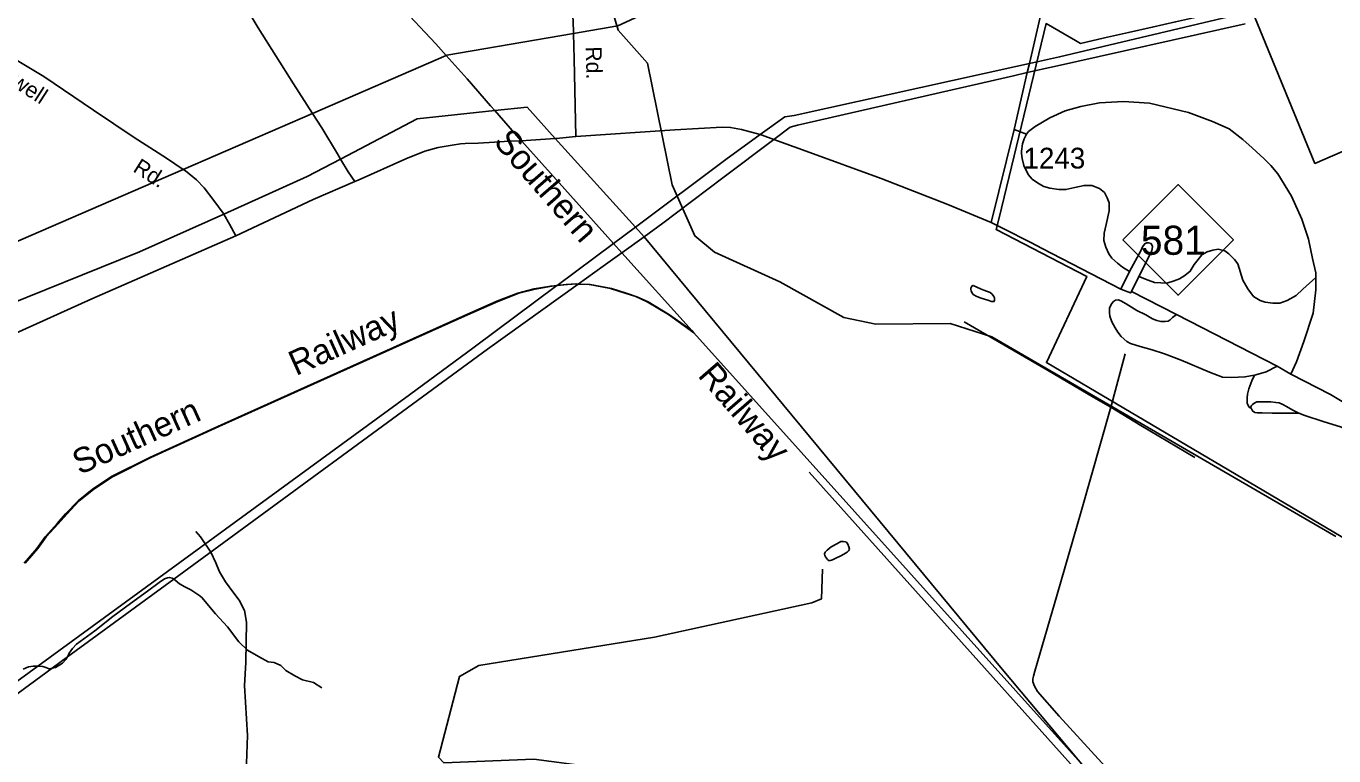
# Model space of a CAD drawing. Extents: x 2260773 to 2342389, y 552869 to 618546.
# Drawn here: x 2280360 to 2288230, y 598847 to 603238 of the extents above; entities that cross this region are included whole.
import ezdxf

# ---------------------------------------------------------------- set-up
doc = ezdxf.new("R2010")
doc.units = 0
for name, color, linetype in [('Exist Boundary Political City Limit New', 7, 'Continuous'), ('Exist Boundary Political Urban Extension UEB', 7, 'Continuous'), ('Exist Hydrographic Creek Single Shore', 7, 'Continuous'), ('Exist Hydrographic Misc Water Feature', 7, 'Continuous'), ('Exist Railroad Mainline', 7, 'Continuous'), ('Exist Railroad Mainline Label', 7, 'Continuous'), ('Exist Railroad Siding', 7, 'Continuous'), ('Exist Road Non-System Type 51', 7, 'Continuous'), ('Exist Road Primary NC Attributed', 7, 'Continuous'), ('Exist Road Primary NC Shield CELL', 7, 'Continuous'), ('Exist Road Primary NC Shield Number Label', 7, 'Continuous'), ('Exist Road Secondary Type 51 Attributed', 7, 'Continuous'), ('Exist Road Secondary Type 51 Label', 7, 'Continuous'), ('Exist Road Secondary Type 51 Number Label', 7, 'Continuous'), ('Exist Utilities Electrical Transmission Line', 7, 'Continuous'), ('Map Preparation Boundary City Limit Buffer Line', 7, 'Continuous')]:
    doc.layers.add(name, color=color, linetype=linetype)

msp = doc.modelspace()

# ---------------------------------------------------------------- linework, layer by layer
at = {"layer": 'Exist Boundary Political City Limit New'}
msp.add_lwpolyline([(2288484.5, 600042.1), (2286500, 601213.4), (2286743.2, 601732.2), (2286198.5, 602014.4), (2286215.2, 602083.9), (2286498, 603253.8), (2286675.8, 603151.9), (2286705.2, 603134.9), (2286849.8, 603167.4), (2286994.2, 603200), (2287137, 603232.2), (2287277.5, 603263.9), (2287421.5, 603296.4), (2287566, 603329), (2287724.2, 603364.7), (2288116, 602412), (2288435.5, 602550.4)], dxfattribs=at)
at = {"layer": 'Exist Boundary Political Urban Extension UEB'}
for p, q in [((2283544.6, 602562.6), (2284026.3, 602029)), ((2284026.3, 602029), (2284079.1, 601970.5))]:
    msp.add_line(p, q, dxfattribs=at)
for points in [[(2283180.3, 602730.4), (2283374.6, 602750.9), (2283544.6, 602562.6)], [(2282251.6, 602438.5), (2282713, 602681.3), (2283180.3, 602730.4)], [(2281548.7, 602107.8), (2282051.3, 602333.1), (2282251.6, 602438.5)], [(2279105.8, 601336.1), (2279230.5, 601149.2), (2281041.4, 601880.4), (2281548.7, 602107.8)], [(2284079.1, 601970.5), (2286234.2, 599368.4), (2286857.2, 598623.6)]]:
    msp.add_lwpolyline(points, dxfattribs=at)
at = {"layer": 'Exist Hydrographic Creek Single Shore'}
for points in [[(2288241.8, 600166.2), (2286172.8, 601369.1), (2285921.9, 601449.6), (2285472.8, 601445.6), (2285280.7, 601485.5), (2284895.8, 601700), (2284502.7, 601878.5), (2284384.8, 601976), (2284248.6, 602283.7), (2284099.8, 603014.8), (2283923.6, 603215.1), (2283845.7, 603472.5), (2284045.6, 604380.1), (2283991.7, 604787.9), (2283797.7, 605087.1), (2283384.7, 605633.3), (2283178.7, 606204.8), (2283010.7, 606362.3), (2282767.7, 606508.3)], [(2286243.8, 593850.9), (2286225.7, 594008.7), (2285935.8, 594772.2), (2285951.8, 595654), (2285602.8, 596490.8), (2285254.8, 597153.8), (2284792.8, 597576.4), (2284607.7, 597790), (2284099.8, 598594), (2283982.7, 598724.2), (2283764.7, 598781.1), (2283414.7, 598827.5), (2282873.8, 598805.7), (2282840.7, 598839.2), (2282968.7, 599325.2), (2283084.8, 599391.8), (2284140.8, 599560.6), (2285088.7, 599767.7), (2285146.8, 599792.7), (2285153.7, 599969.7)]]:
    msp.add_lwpolyline(points, dxfattribs=at)
at = {"layer": 'Exist Hydrographic Misc Water Feature'}
for points in [[(2286103.5, 601656.7), (2286081.2, 601668.2), (2286059, 601678.1), (2286051, 601674), (2286049.6, 601670.1), (2286045.3, 601662.3), (2286045.7, 601654.1), (2286047.8, 601646.1), (2286052.1, 601636.1), (2286059.9, 601624), (2286082.2, 601610.5), (2286108.2, 601600.5), (2286148, 601589.2), (2286170, 601581.4), (2286176.3, 601581.3), (2286184.5, 601581.3), (2286188, 601587.2), (2286188, 601595.3), (2286188.2, 601603.4), (2286183.5, 601611.4), (2286173.5, 601625.1), (2286162, 601635), (2286123.4, 601648.9), (2286103.5, 601656.7)], [(2281382, 600196.8), (2281409.9, 600165), (2281471, 600071.9), (2281501.5, 600008.1), (2281524.1, 599954.4), (2281560.4, 599894.6), (2281603.3, 599835), (2281641.4, 599783.4), (2281674, 599721.8), (2281685.1, 599652), (2281681.4, 599408), (2281674.6, 599270.3), (2281691, 598968.6), (2281683.6, 598744.6), (2281676.3, 598450.5), (2281681.2, 598304.6), (2281672.2, 598198.9), (2281669.9, 598082.8), (2281672.2, 598012.7), (2281682.6, 597962.9), (2281707, 597905.3)], [(2285193.7, 600020.8), (2285213, 600027.3), (2285233.3, 600037.1), (2285263, 600051.8), (2285281.3, 600061.5), (2285300.8, 600072), (2285309, 600080.1), (2285312.9, 600086), (2285314.9, 600090.2), (2285310.6, 600105.8), (2285304.6, 600120.1), (2285296.2, 600133.9), (2285290.1, 600135.7), (2285276.6, 600137.7), (2285264, 600137.6), (2285238.4, 600123.2), (2285204.8, 600105.1), (2285181, 600084.8), (2285168.7, 600072.8), (2285165, 600062.5), (2285167.1, 600052.8), (2285171.4, 600044.5), (2285183.1, 600028.9), (2285193.7, 600020.8)]]:
    msp.add_lwpolyline(points, dxfattribs=at)
at = {"layer": 'Exist Railroad Mainline'}
msp.add_line((2284378.9, 601393.8), (2284368.5, 601405.4), dxfattribs=at)
for points in [[(2283339.6, 602549.2), (2283180.3, 602730.4), (2283154.7, 602759.6), (2283013.2, 602922.3), (2282888.6, 603061.7), (2282825.4, 603132.4), (2282603.2, 603368.2), (2282433.6, 603560.6), (2282271.8, 603747), (2282045.7, 603992.7), (2281744.6, 604327.7), (2281506.4, 604579.3), (2281381.3, 604706), (2281286.5, 604793.1), (2281212.1, 604860.4), (2281147.6, 604913.8), (2281105.1, 604951.3), (2281042.9, 604994.7), (2280956.2, 605051.9), (2280885.9, 605103.3), (2279466.6, 606053.8)], [(2284368.5, 601405.4), (2283945.9, 601875.1), (2283895.4, 601931.3), (2283342.6, 602545.7), (2283339.6, 602549.2)], [(2287893.8, 597482.5), (2286781.2, 598720.6), (2286638.8, 598879), (2284378.9, 601393.8)]]:
    msp.add_lwpolyline(points, dxfattribs=at)
at = {"layer": 'Exist Railroad Siding'}
for points in [[(2283750, 601683.7), (2283748.4, 601684), (2283683, 601686.6), (2283668.5, 601687.2), (2283610.5, 601684.6), (2283556.1, 601678.3), (2283516.7, 601673.7), (2283417, 601656.7), (2283319.3, 601631.9), (2283191.7, 601582.7), (2282990.6, 601492.8), (2281513.7, 600829.3), (2281103.7, 600643.5), (2280873, 600527.4), (2280757.7, 600450.4), (2280672.3, 600381.7), (2280597.1, 600302.9), (2280545.8, 600244.5), (2280474.6, 600165.8), (2280423.2, 600095.5), (2280348, 600006.8)], [(2283750, 601683.7), (2283682.7, 601686.4), (2283675.1, 601686.7), (2283617.1, 601684.1), (2283554.1, 601676.8), (2283523.3, 601673.2), (2283423.6, 601656.2), (2283325.9, 601631.4), (2283198.3, 601582.2), (2282997.2, 601492.3), (2281520.3, 600828.8), (2281110.3, 600643), (2280879.6, 600526.9), (2280764.3, 600449.9), (2280678.9, 600381.2), (2280603.7, 600302.4), (2280552.4, 600244), (2280481.2, 600165.3), (2280429.8, 600095), (2280354.6, 600006.3)], [(2284368.5, 601405.4), (2284232.5, 601502), (2284103.9, 601578.6), (2284035.6, 601610), (2283971.5, 601631.5), (2283883.2, 601658.7), (2283755, 601683.5), (2283750, 601683.7)], [(2284378.9, 601393.8), (2284225.9, 601502.5), (2284097.3, 601579.1), (2284029, 601610.5), (2283964.9, 601632), (2283876.6, 601659.2), (2283750, 601683.7)]]:
    msp.add_lwpolyline(points, dxfattribs=at)
at = {"layer": 'Exist Road Non-System Type 51'}
for p, q in [((2286306.3, 602615.5), (2286379.7, 602588.5)), ((2286378.7, 602584.3), (2286380.6, 602588.2)), ((2286379.7, 602588.5), (2286380.6, 602588.2)), ((2286949, 601655.9), (2286999.9, 601762.5)), ((2287011.9, 601642.1), (2287056.3, 601730.9)), ((2286900.4, 600990.6), (2286975, 601267.1)), ((2286888, 600944.7), (2286899.6, 600987.7)), ((2286899.6, 600987.7), (2286900.4, 600990.6)), ((2285072.4, 600554.9), (2286594.7, 598855.2)), ((2286594.7, 598855.2), (2286696, 598742.1))]:
    msp.add_line(p, q, dxfattribs=at)
for points in [[(2281036.8, 603990.4), (2281121.5, 604000.1), (2281177.2, 604007.4), (2281211.1, 604009.8), (2281230.5, 604007.4), (2281252.3, 604002.6), (2281271.6, 603992.9), (2281293.4, 603961.4), (2281361.2, 603852.4), (2281433.9, 603762.7), (2281472.6, 603702.2), (2281542.8, 603585.9), (2281755.9, 603227.4), (2281968.9, 602890.7), (2282083, 602712.9)], [(2286380.6, 602588.2), (2286392.5, 602604.3), (2286432.1, 602634.7), (2286521.5, 602687.5), (2286613.1, 602728.2), (2286706.8, 602755.1), (2286820.6, 602776.1), (2286964.3, 602785.4), (2287120.5, 602775.1), (2287354.8, 602719.3), (2287499.3, 602664.6), (2287599.5, 602619.6), (2287682.2, 602556.3), (2287738.6, 602507), (2287811.2, 602439.7), (2287851.6, 602400.1), (2287894, 602350.5), (2287975.2, 602215.3), (2288038.5, 602076), (2288077.5, 601956.5), (2288102.7, 601840.6), (2288121.5, 601752.9), (2288121.8, 601724.9)], [(2282083, 602712.9), (2282138.4, 602626.6), (2282232.8, 602469.2), (2282251.6, 602438.5)], [(2286351, 602471.4), (2286349.5, 602485.8), (2286357.2, 602529.8), (2286366.8, 602560), (2286378.7, 602584.3)], [(2282251.6, 602438.5), (2282298.2, 602362.6), (2282337.8, 602303)], [(2286999.9, 601762.5), (2286957.7, 601787.9), (2286927.6, 601811.7), (2286893.4, 601841.4), (2286877, 601869.1), (2286858.8, 601908.9), (2286846.4, 601948.9), (2286847.9, 601992.9), (2286859.3, 602044.8), (2286878.6, 602127), (2286878.2, 602175), (2286866, 602204.8), (2286849.6, 602236.7), (2286819.4, 602262.4), (2286773.1, 602279.9), (2286727.4, 602279.6), (2286671.3, 602267), (2286617.5, 602254.5), (2286575.5, 602256.1), (2286521.5, 602263.6), (2286485.5, 602273.3), (2286453.3, 602291), (2286415.1, 602318.5), (2286390.8, 602346.4), (2286364.3, 602400.1), (2286354, 602441.9), (2286351, 602471.4)], [(2286999.9, 601762.5), (2287070.7, 601891), (2287078.5, 601911), (2287092.3, 601929.1), (2287104.2, 601935.3), (2287114.2, 601935.3), (2287130.3, 601929.6), (2287138.5, 601911.6), (2287134.8, 601885.7), (2287056.3, 601730.9)], [(2287056.3, 601730.9), (2287112.4, 601709.4), (2287150.5, 601695.8), (2287188.5, 601694.3), (2287224.4, 601692.5), (2287268.3, 601704.8), (2287302.3, 601717.3), (2287334.1, 601737.5), (2287365.8, 601763.8), (2287389.4, 601803.9), (2287413, 601834.2), (2287436.8, 601862.4), (2287468.6, 601880.7), (2287502.6, 601891), (2287534.4, 601895.4), (2287574.4, 601885.7), (2287598.7, 601867.9), (2287633, 601834.4), (2287653.2, 601808.6), (2287682.2, 601708.8), (2287712.5, 601657.2), (2287747, 601611.5), (2287787.1, 601587.9), (2287817.3, 601578.1), (2287863.3, 601570.6), (2287905.3, 601570.9), (2287949, 601587.4), (2288002.8, 601617.9), (2288044.4, 601656.3), (2288121.8, 601724.9)], [(2288121.8, 601724.9), (2288122.5, 601650.9), (2288105.8, 601510.9), (2288050.5, 601341.1), (2288005.5, 601219.1), (2287972.1, 601143.6)], [(2287284.2, 601503.8), (2287259.5, 601484.9), (2287245, 601471.8), (2287233.4, 601463.1), (2287214.5, 601460.2), (2287189.8, 601461.7), (2287165.2, 601467.5), (2287139, 601477.6), (2287098.4, 601500.9), (2287044.7, 601527), (2286979.4, 601567.7), (2286947.5, 601585.1), (2286931.5, 601590.9), (2286917, 601589.4), (2286903.9, 601582.2), (2286892.3, 601567.7), (2286880.7, 601541.5), (2286879.3, 601513.9), (2286882.2, 601493.6), (2286894.8, 601459.5), (2286913.3, 601423.7), (2286929.4, 601397.8), (2286950.4, 601371.6), (2286985.2, 601339.7), (2287007, 601328.1), (2287065, 601310.6), (2287136.1, 601290.3), (2287210.2, 601267.1), (2287311.7, 601229.3), (2287481.5, 601155.3), (2287559.9, 601126.2), (2287613.6, 601124.8), (2287694.9, 601127.7), (2287753.7, 601137.9)], [(2286888, 600944.7), (2286786.4, 601002.8), (2286506.3, 601168.3), (2286005.6, 601458.7)], [(2287753.7, 601137.9), (2287761.6, 601139.3), (2287822.6, 601158.2), (2287889.4, 601191.6)], [(2287753.7, 601137.9), (2287737, 601104.4), (2287719.6, 601056.5), (2287710.9, 601024.6), (2287709.4, 601001.3), (2287708, 600985.4), (2287709.4, 600969.4), (2287716.7, 600952), (2287722.5, 600943.2), (2287732.6, 600938.9)], [(2286888, 600944.7), (2286709.5, 600317.4), (2286564.3, 599817.9), (2286445.3, 599405.5), (2286431, 599357.1)], [(2286888, 600944.7), (2287069.4, 600834.3), (2287393, 600642.7)], [(2288020, 600908.4), (2287983.7, 600927.3), (2287944.5, 600949.1), (2287924.2, 600960.7), (2287901, 600970.8), (2287880.7, 600973.7), (2287851.6, 600976.6), (2287822.6, 600978.1), (2287792.1, 600976.6), (2287767.5, 600976.6), (2287754.4, 600970.8), (2287741.3, 600962.1), (2287734.1, 600954.9), (2287731.2, 600947.6), (2287732.6, 600938.9)], [(2287732.6, 600938.9), (2287741.3, 600922.9), (2287754.4, 600914.2), (2287770.4, 600911.3), (2287799.4, 600911.3), (2287858.9, 600909.8), (2287943.1, 600908.4), (2288020, 600908.4)], [(2288020, 600908.4), (2288054.8, 600895.3), (2288165.1, 600859), (2288276.9, 600825.6), (2288308.8, 600811.1), (2288332, 600802.4), (2288348, 600795.1), (2288366.8, 600793.7), (2288387.2, 600793.7), (2288414.7, 600795.1), (2288435.1, 600799.5), (2288455.4, 600811.1), (2288478.6, 600822.7), (2288498.9, 600834.3)], [(2280609.5, 599442.4), (2280610.8, 599444.5), (2280619, 599466), (2280638.9, 599492.5), (2280663.7, 599519), (2280772.9, 599598.5), (2280882.1, 599686.2), (2280988, 599764), (2281090.6, 599838.5), (2281160.1, 599889.9), (2281193.2, 599913), (2281209.8, 599918), (2281223, 599921.3), (2281237.9, 599916.4), (2281247.7, 599910.1)], [(2281247.7, 599910.1), (2281256.1, 599904.8), (2281282.6, 599883.2), (2281314, 599865), (2281350.4, 599845.2), (2281405, 599810.4), (2281419.9, 599798.8), (2281446.4, 599764), (2281499.3, 599701.1), (2281572.1, 599623.3), (2281640, 599532.3), (2281691.3, 599482.6), (2281759.1, 599444.5), (2281815.4, 599413.1), (2281853.4, 599408.1), (2281893.1, 599389.9), (2281922.9, 599361.7), (2281975.9, 599328.6), (2282022.2, 599303.8), (2282090, 599288.9), (2282139.7, 599257.4)], [(2280516.9, 599374.7), (2280536.3, 599378.3), (2280552.9, 599388.2), (2280572.7, 599401.5), (2280579.3, 599404.8), (2280599.2, 599426.3), (2280609.5, 599442.4)], [(2280342.7, 599368.4), (2280374.1, 599383.3), (2280402.3, 599386.6), (2280428.8, 599386.6), (2280429.1, 599386.5)], [(2280429.1, 599386.5), (2280460.2, 599384.9), (2280478.4, 599378.3), (2280498.2, 599371.7), (2280509.8, 599373.3), (2280516.9, 599374.7)], [(2286431, 599357.1), (2286422.1, 599327), (2286417.7, 599309.6), (2286419.2, 599292.2), (2286427.9, 599266.1), (2286446, 599234.4), (2286577.4, 599085.8), (2287112.7, 598501.1), (2287480.9, 598094.7)]]:
    msp.add_lwpolyline(points, dxfattribs=at)
at = {"layer": 'Exist Road Primary NC Attributed'}
for points in [[(2283668.5, 602574.1), (2283570, 602564.4), (2283544.6, 602562.6), (2283397.2, 602552.1), (2283339.6, 602549.2)], [(2286167.6, 602056.5), (2285907.2, 602165.6), (2285505.3, 602322.2), (2285054.9, 602485.3), (2284860.3, 602556.6), (2284790.2, 602582.2), (2284778.5, 602585.4), (2284666, 602616.1), (2284599.8, 602629), (2284548.1, 602630.7), (2284264.1, 602614.5), (2283668.5, 602574.1)], [(2283339.6, 602549.2), (2283266.5, 602545.5), (2283179.4, 602539.4), (2283080.2, 602534.6), (2283002.7, 602532.1), (2282973.6, 602529.7), (2282924.1, 602522.9), (2282839.6, 602509), (2282758.5, 602485.9), (2282644.4, 602439.5), (2282357.3, 602312.4), (2282337.8, 602303), (2282086.7, 602194.5), (2281621.8, 601975.9)], [(2289571.4, 598974.2), (2289374.1, 599312.5), (2289105.2, 599815.2), (2288844.6, 600320.5), (2288699.2, 600577.3), (2288644, 600671.7), (2288578.5, 600755.7), (2288535.2, 600803.8), (2288498.9, 600834.3), (2288455.4, 600870.6), (2288365.4, 600928.7), (2288210.1, 601021.7), (2287972.1, 601143.6), (2287889.4, 601191.6), (2287284.2, 601503.8), (2287011.9, 601642.1), (2287007.1, 601632.6), (2286949, 601655.9), (2286475.6, 601901), (2286406.7, 601936.7), (2286240.2, 602020.1), (2286239.7, 602020.4), (2286167.6, 602056.5)], [(2281621.8, 601975.9), (2280754.7, 601596.8), (2280274.9, 601381.6), (2279715.8, 601136.3), (2279285.4, 600941.2), (2279144.7, 600873.3)]]:
    msp.add_lwpolyline(points, dxfattribs=at)
at = {"layer": 'Exist Road Primary NC Shield CELL'}
msp.add_lwpolyline([(2286959.9, 601952.1), (2287292.9, 602285.1), (2287625.9, 601952.1), (2287292.9, 601619.1)], close=True, dxfattribs=at)
at = {"layer": 'Exist Road Secondary Type 51 Attributed'}
for points in [[(2283033.1, 604532.5), (2283142.8, 604360.3), (2283239.2, 604205.2), (2283376.3, 603987.2), (2283495.8, 603790.2), (2283562, 603649.7), (2283594.2, 603564.1), (2283623.3, 603483.3), (2283637.8, 603399.4), (2283652.3, 603271.8), (2283654.5, 603194.6), (2283658.8, 603040.9), (2283668.5, 602574.1)], [(2286485.2, 603390.4), (2286468.6, 603318.6), (2286398.2, 603013.5), (2286385.5, 602958.7), (2286306.3, 602615.5), (2286167.6, 602056.5)], [(2281621.8, 601975.9), (2281584.3, 602045.8), (2281548.7, 602107.8), (2281546.2, 602112.1), (2281489.9, 602189.9), (2281432, 602266), (2281385.7, 602314.1), (2281319.5, 602367), (2281305.7, 602376.5), (2281205.3, 602444.8), (2281010.1, 602569), (2280765.2, 602732.9), (2280465.7, 602934.9), (2280215.8, 603085.6), (2280032.2, 603184.9), (2279931.9, 603235.1)]]:
    msp.add_lwpolyline(points, dxfattribs=at)
at = {"layer": 'Exist Utilities Electrical Transmission Line'}
for p, q in [((2282888.6, 603061.7), (2282083, 602712.9)), ((2286398.2, 603013.5), (2286315.6, 602995.3)), ((2286385.5, 602958.7), (2286475.7, 602979.2)), ((2286489, 603033.6), (2286398.2, 603013.5)), ((2286302.2, 602939.6), (2286385.5, 602958.7)), ((2282083, 602712.9), (2281305.7, 602376.5)), ((2283895.4, 601931.3), (2284026.3, 602029)), ((2284079.1, 601970.5), (2283945.9, 601875.1)), ((2283556.1, 601678.3), (2283895.4, 601931.3)), ((2283554.1, 601676.8), (2283556.1, 601678.3)), ((2283683, 601686.6), (2283682.7, 601686.4)), ((2280609.5, 599442.4), (2281247.7, 599910.1)), ((2280516.9, 599374.7), (2280609.5, 599442.4))]:
    msp.add_line(p, q, dxfattribs=at)
for points in [[(2285134.4, 603802.1), (2283921.7, 603240.7), (2283654.5, 603194.6)], [(2287673.1, 603313), (2286580.1, 603053.7), (2286489, 603033.6)], [(2286475.7, 602979.2), (2286482.9, 602980.9), (2286530.7, 602991.4), (2287696.4, 603252.2)], [(2283654.5, 603194.6), (2282891.9, 603063.1), (2282888.6, 603061.7)], [(2286315.6, 602995.3), (2284982.2, 602700.9), (2284926.4, 602692.5), (2284778.5, 602585.4)], [(2286302.2, 602939.6), (2285002.8, 602643.1), (2284959, 602630.8), (2284860.3, 602556.6)], [(2284026.3, 602029), (2284570.9, 602435.2), (2284778.5, 602585.4)], [(2284860.3, 602556.6), (2284552.1, 602325), (2284192.7, 602051.8), (2284079.1, 601970.5)], [(2281305.7, 602376.5), (2279648.8, 601659.3), (2279613.1, 601641), (2279579.3, 601622.7), (2279523.7, 601582.2), (2279105.8, 601336.1)], [(2283945.9, 601875.1), (2283833.4, 601794.6), (2283683, 601686.6)], [(2280429.1, 599386.5), (2282667.3, 601020), (2283056.4, 601305.6), (2283554.1, 601676.8)], [(2283682.7, 601686.4), (2283136.5, 601294.3), (2281247.7, 599910.1)], [(2280429.1, 599386.5), (2279945.4, 599033.6), (2279554.2, 598762), (2276202.5, 597215.3), (2273346.6, 595901.2), (2272928.5, 595719.3), (2272512.5, 595535.4), (2272145.9, 595392.1), (2272049.1, 595358.1)], [(2272051.3, 595276.1), (2272178.6, 595328.5), (2272535, 595473.8), (2272963.1, 595651.7), (2273381.1, 595845.5), (2276661.1, 597333.5), (2279596.8, 598700.4), (2280516.9, 599374.7)]]:
    msp.add_lwpolyline(points, dxfattribs=at)
at = {"layer": 'Map Preparation Boundary City Limit Buffer Line'}
msp.add_lwpolyline([(2288484.5, 600042.1), (2286500, 601213.4), (2286743.2, 601732.2), (2286198.5, 602014.4), (2286215.2, 602083.9), (2286498, 603253.8), (2286675.8, 603151.9), (2286705.2, 603134.9), (2286849.8, 603167.4), (2286994.2, 603200), (2287137, 603232.2), (2287277.5, 603263.9), (2287421.5, 603296.4), (2287566, 603329), (2287724.2, 603364.7), (2288116, 602412), (2288435.5, 602550.4)], dxfattribs=at)

# ---------------------------------------------------------------- texts
at = {"layer": 'Exist Railroad Mainline Label'}
for s, rotation, p in [('Southern', 310.96977, (2283167.3, 602538.9)), ('Railway', 24.29712, (2281983.6, 601131.8)), ('Railway', 310.96977, (2284397.1, 601133.7)), ('Southern', 24.29712, (2280681.3, 600536.1))]:
    msp.add_text(s, height=150, rotation=rotation, dxfattribs=at).set_placement(p)
at = {"layer": 'Exist Road Primary NC Shield Number Label'}
msp.add_text('581', height=175, dxfattribs=at).set_placement((2287069, 601862.4))
at = {"layer": 'Exist Road Secondary Type 51 Label'}
for s, rotation, p in [('Hollowell', 327.15292, (2280020.7, 603040.7)), ('Rd.', 271.24202, (2283727.7, 603115.3)), ('Rd.', 327.61518, (2280996.8, 602366.8))]:
    msp.add_text(s, height=95, rotation=rotation, dxfattribs=at).set_placement(p)
at = {"layer": 'Exist Road Secondary Type 51 Number Label'}
msp.add_text('1243', height=125, dxfattribs=at).set_placement((2286362.4, 602381.6))

doc.saveas('drawing.dxf')
